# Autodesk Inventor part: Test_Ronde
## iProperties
Created: 2006-08
Material: Standard
Document SubType Name: Modeling
Part Number: Test_Ronde
Title: Ronde
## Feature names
1. Drehung1 [Revolution]
2. Rundung1 [Fillet]
3. Fase1 [Chamfer]
